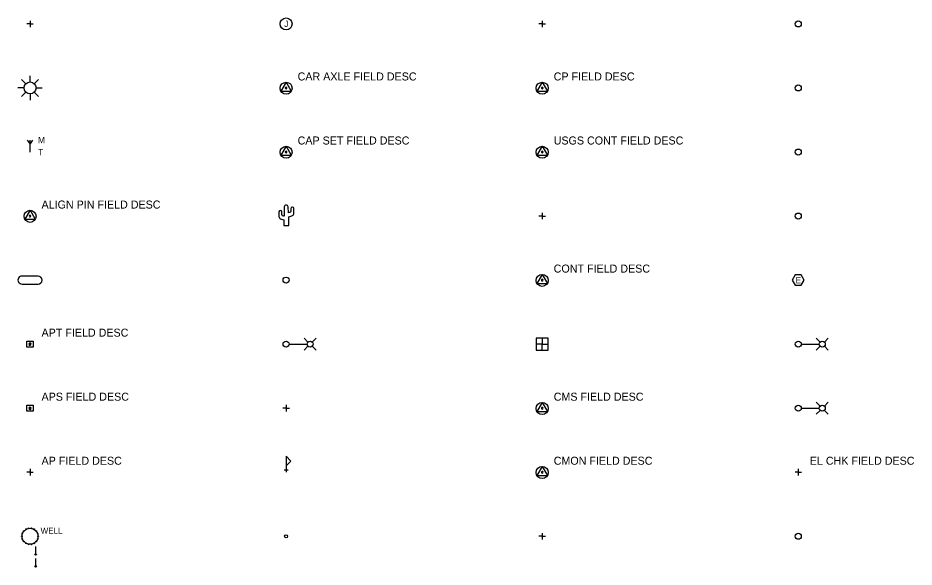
# Model space of a CAD drawing. Extents: x 91 to 2906, y -24 to 912.
# Drawn here: x 91 to 790, y -24 to 405 of the extents above; entities that cross this region are included whole.
import ezdxf

# ---------------------------------------------------------------- set-up
doc = ezdxf.new("R2010")
doc.units = 0
for name, color, linetype in [('B-BORE-CONE', 7, 'Continuous'), ('V-AERI-PNPT', 7, 'Continuous'), ('V-AFLD-DEVC', 7, 'Continuous'), ('V-CHAN-NAID', 7, 'Continuous'), ('V-COMM-ANTN', 7, 'Continuous'), ('V-COMM-JBOX', 7, 'Continuous'), ('V-CTRL-BMRK', 7, 'Continuous'), ('V-CTRL-HVPT', 7, 'Continuous'), ('V-CTRL-VERT', 7, 'Continuous'), ('V-FUEL-DEVC', 7, 'Continuous'), ('V-POWR-METR', 7, 'Continuous'), ('V-POWR-POLE', 7, 'Continuous'), ('V-RAIL-EQPM', 7, 'Continuous'), ('V-SITE-OTLN', 7, 'Continuous'), ('V-SITE-STRC', 7, 'Continuous'), ('V-SITE-VEGE', 7, 'Continuous'), ('V-SURV-DATA', 7, 'Continuous'), ('V-TOPO-SPOT', 7, 'Continuous')]:
    doc.layers.add(name, color=color, linetype=linetype)

msp = doc.modelspace()

# ---------------------------------------------------------------- linework, layer by layer
at = {"layer": 'B-BORE-CONE'}
for points in [[(495.31, 145.31), (504.69, 145.31), (504.69, 154.69), (495.31, 154.69)], [(500, 150), (504.69, 150), (504.69, 154.69), (500, 154.69)], [(495.31, 145.31), (500, 145.31), (500, 150), (495.31, 150)]]:
    msp.add_lwpolyline(points, close=True, dxfattribs=at)
at = {"layer": 'V-AERI-PNPT'}
for p, q in [((99.53, 150), (100.47, 150)), ((99.53, 100), (100.47, 100))]:
    msp.add_line(p, q, dxfattribs=at)
for points in [[(97.58, 152.42), (102.42, 152.42), (102.42, 147.58), (97.58, 147.58)], [(97.58, 102.42), (102.42, 102.42), (102.42, 97.58), (97.58, 97.58)]]:
    msp.add_lwpolyline(points, close=True, dxfattribs=at)
for centre, radius, start, end in [((100, 150), 0.909, 91.4818, 90.9603), ((100, 150), 0.455, 95.64757, 94.60838), ((100, 100), 0.909, 91.4818, 90.9603), ((100, 100), 0.455, 95.64757, 94.60838)]:
    msp.add_arc(centre, radius, start, end, dxfattribs=at)
at = {"layer": 'V-AFLD-DEVC'}
for p, q in [((100, 354.69), (100, 359.44)), ((95.31, 350), (90.56, 350)), ((96.69, 353.31), (93.31, 356.69)), ((103.31, 353.31), (106.69, 356.69)), ((104.69, 350), (109.44, 350)), ((96.69, 346.69), (93.31, 343.31)), ((100, 345.31), (100, 340.56)), ((103.31, 346.69), (106.69, 343.31))]:
    msp.add_line(p, q, dxfattribs=at)
msp.add_circle((100, 350), 4.69, dxfattribs=at)
at = {"layer": 'V-CHAN-NAID'}
for p, q in [((298.54, 51.91), (301.66, 51.91)), ((300, 54.98), (300, 50))]:
    msp.add_line(p, q, dxfattribs=at)
msp.add_lwpolyline([(300, 54.98), (303.76, 58.75), (300, 62.51)], close=True, dxfattribs=at)
at = {"layer": 'V-COMM-ANTN'}
msp.add_line((100, 300), (100, 309.37), dxfattribs=at)
msp.add_lwpolyline([(97.88, 309.37), (100, 306.19), (102.12, 309.37)], dxfattribs=at)
at = {"layer": 'V-COMM-JBOX'}
msp.add_circle((300, 400), 4.69, dxfattribs=at)
at = {"layer": 'V-FUEL-DEVC'}
for p, q in [((93.65, 0), (93.65, 0)), ((94.03, 2.18), (94.03, 2.18)), ((95.13, 4.09), (95.13, 4.09)), ((96.82, 5.5), (96.82, 5.5)), ((98.9, 6.25), (98.9, 6.25)), ((101.11, 6.25), (101.11, 6.25)), ((103.18, 5.5), (103.18, 5.5)), ((104.87, 4.09), (104.87, 4.09)), ((105.97, 2.18), (105.97, 2.18)), ((106.35, 0), (106.35, 0)), ((94.03, -2.18), (94.03, -2.18)), ((95.13, -4.09), (95.13, -4.09)), ((96.82, -5.5), (96.82, -5.5)), ((98.9, -6.25), (98.9, -6.25)), ((101.11, -6.25), (101.11, -6.25)), ((103.18, -5.5), (103.18, -5.5)), ((104.87, -4.09), (104.87, -4.09)), ((105.97, -2.18), (105.97, -2.18)), ((104.42, -7.94), (104.42, -13.59)), ((104.42, -17.24), (104.42, -22.89))]:
    msp.add_line(p, q, dxfattribs=at)
for centre, radius in [((93.65, 0), 0.282), ((94.03, 2.17), 0.282), ((100, 0), 6.24), ((95.14, 4.08), 0.282), ((96.83, 5.5), 0.282), ((98.9, 6.25), 0.282), ((101.1, 6.25), 0.282), ((103.18, 5.5), 0.282), ((104.86, 4.08), 0.282), ((105.97, 2.17), 0.282), ((106.35, 0), 0.282), ((94.03, -2.17), 0.282), ((95.14, -4.08), 0.282), ((96.83, -5.5), 0.282), ((98.9, -6.25), 0.282), ((101.1, -6.25), 0.282), ((103.18, -5.5), 0.282), ((104.86, -4.08), 0.282), ((105.97, -2.17), 0.282), ((104.42, -14.15), 0.564), ((104.42, -23.46), 0.564)]:
    msp.add_circle(centre, radius, dxfattribs=at)
at = {"layer": 'V-POWR-METR'}
msp.add_lwpolyline([(702.34, 195.94), (704.69, 200), (702.34, 204.06), (697.66, 204.06), (695.31, 200), (697.66, 195.94)], close=True, dxfattribs=at)
at = {"layer": 'V-POWR-POLE'}
for centre in [(700, 400), (700, 350), (700, 300), (700, 250), (300, 200), (700, 0)]:
    msp.add_circle(centre, 2.34, dxfattribs=at)
at = {"layer": 'V-RAIL-EQPM'}
msp.add_circle((300, 0), 1.17, dxfattribs=at)
at = {"layer": 'V-SITE-OTLN'}
for p, q in [((317.09, 151.66), (314.06, 154.69)), ((320.41, 151.66), (323.44, 154.69)), ((717.09, 151.66), (714.06, 154.69)), ((720.41, 151.66), (723.44, 154.69)), ((302.34, 150), (316.41, 150)), ((317.09, 148.34), (314.06, 145.31)), ((320.41, 148.34), (323.44, 145.31)), ((702.34, 150), (716.41, 150)), ((717.09, 148.34), (714.06, 145.31)), ((720.41, 148.34), (723.44, 145.31)), ((300, 100), (297.46, 100)), ((300, 102.55), (300, 97.46)), ((300, 100), (302.55, 100)), ((702.34, 100), (716.41, 100)), ((717.09, 101.66), (714.06, 104.69)), ((717.09, 98.34), (714.06, 95.31)), ((720.41, 101.66), (723.44, 104.69)), ((720.41, 98.34), (723.44, 95.31))]:
    msp.add_line(p, q, dxfattribs=at)
for centre in [(300, 150), (318.75, 150), (700, 150), (718.75, 150), (700, 100), (718.75, 100)]:
    msp.add_circle(centre, 2.34, dxfattribs=at)
at = {"layer": 'V-SITE-STRC'}
for p, q in [((106.25, 203.13), (93.75, 203.13)), ((93.75, 196.87), (106.25, 196.87))]:
    msp.add_line(p, q, dxfattribs=at)
for centre, start_param, end_param in [((93.75, 200), 0, 3.141593), ((106.25, 200), 3.141593, 6.283185)]:
    msp.add_ellipse(centre, major_axis=(0, 3.13), ratio=0.999658, start_param=start_param, end_param=end_param, dxfattribs=at)
at = {"layer": 'V-SITE-VEGE'}
for p, q in [((294.44, 253.39), (294.45, 249.71)), ((296.66, 250.94), (296.65, 253.32)), ((303.8, 255.81), (303.72, 253.54)), ((306.02, 251.72), (306.03, 255.51))]:
    msp.add_line(p, q, dxfattribs=at)
for points in [[(298.62, 257.19), (298.42, 250.01), (297.64, 250.08)], [(303.49, 253.09), (301.77, 252.48), (301.62, 257.18)], [(295.48, 247.92), (298.21, 247.02), (298.21, 242.64)], [(298.21, 242.64), (302.05, 242.64), (302.05, 249.51), (304.59, 250.31)]]:
    msp.add_lwpolyline(points, dxfattribs=at)
for centre, radius, start, end in [((295.54, 253.22), 1.11, 4.76961, 171.44108), ((300.12, 257.13), 1.5, 1.87586, 177.61223), ((303.07, 253.6), 0.659, 310.24132, 354.97177), ((304.94, 255.83), 1.14, 343.59093, 180.84359), ((296.35, 249.61), 1.9, 176.81617, 242.70551), ((297.74, 251.18), 1.1, 192.63471, 264.81207), ((304.49, 251.84), 1.53, 273.60935, 355.59578)]:
    msp.add_arc(centre, radius, start, end, dxfattribs=at)
at = {"layer": 'V-SURV-DATA'}
for p, q in [((300, 354.48), (295.95, 347.46)), ((300, 354.48), (304.05, 347.46)), ((500, 354.48), (495.95, 347.46)), ((500, 354.48), (504.05, 347.46)), ((295.95, 347.46), (304.05, 347.46)), ((495.95, 347.46), (504.05, 347.46)), ((300, 304.48), (295.95, 297.46)), ((300, 304.48), (304.05, 297.46)), ((500, 304.48), (495.95, 297.46)), ((500, 304.48), (504.05, 297.46)), ((295.95, 297.46), (304.05, 297.46)), ((495.95, 297.46), (504.05, 297.46)), ((100, 254.48), (95.95, 247.46)), ((100, 254.48), (104.05, 247.46)), ((95.95, 247.46), (104.05, 247.46)), ((500, 204.48), (495.95, 197.46)), ((500, 204.48), (504.05, 197.46)), ((495.95, 197.46), (504.05, 197.46)), ((500, 104.48), (495.95, 97.46)), ((500, 104.48), (504.05, 97.46)), ((495.95, 97.46), (504.05, 97.46)), ((100, 50), (97.46, 50)), ((100, 52.55), (100, 47.46)), ((100, 50), (102.55, 50)), ((500, 54.48), (495.95, 47.46)), ((500, 54.48), (504.05, 47.46)), ((700, 50), (697.46, 50)), ((700, 52.55), (700, 47.46)), ((700, 50), (702.55, 50)), ((495.95, 47.46), (504.05, 47.46)), ((500, 2.55), (500, -2.54)), ((500, 0), (497.46, 0)), ((500, 0), (502.55, 0))]:
    msp.add_line(p, q, dxfattribs=at)
for centre in [(300, 349.8), (500, 349.8), (300, 299.8), (500, 299.8), (100, 249.8), (500, 199.8), (500, 99.8), (500, 49.8)]:
    msp.add_circle(centre, 4.69, dxfattribs=at)
for centre in [(300, 350), (500, 350), (300, 300), (500, 300), (100, 250), (500, 200), (500, 100), (500, 50)]:
    msp.add_arc(centre, 0.65, 92.28772, 90.56743, dxfattribs=at)
at = {"layer": 'V-TOPO-SPOT'}
for p, q in [((100, 400), (97.46, 400)), ((100, 402.55), (100, 397.46)), ((100, 400), (102.55, 400)), ((500, 400), (497.46, 400)), ((500, 402.55), (500, 397.46)), ((500, 400), (502.55, 400)), ((500, 252.55), (500, 247.46)), ((500, 250), (497.46, 250)), ((500, 250), (502.55, 250))]:
    msp.add_line(p, q, dxfattribs=at)

# ---------------------------------------------------------------- texts
at = {"layer": 'V-AERI-PNPT'}
for s, p in [('APT FIELD DESC', (109, 155.87)), ('APS FIELD DESC', (109, 105.87)), ('AP FIELD DESC', (109, 55.87))]:
    msp.add_text(s, height=6.252, dxfattribs=at).set_placement(p)
at = {"layer": 'V-COMM-ANTN'}
for s, p in [('M', (106.25, 306.91)), ('T', (106.25, 297.54))]:
    msp.add_text(s, height=4.92, dxfattribs=at).set_placement(p)
at = {"layer": 'V-COMM-JBOX'}
msp.add_text('J', height=4.92, dxfattribs=at).set_placement((298.55, 397.54))
at = {"layer": 'V-CTRL-BMRK'}
for s, p in [('USGS CONT FIELD DESC', (509, 305.87)), ('CONT FIELD DESC', (509, 205.87))]:
    msp.add_text(s, height=6.252, dxfattribs=at).set_placement(p)
at = {"layer": 'V-CTRL-HVPT'}
msp.add_text('CP FIELD DESC', height=6.252, dxfattribs=at).set_placement((509, 355.87))
at = {"layer": 'V-CTRL-VERT'}
msp.add_text('EL CHK FIELD DESC', height=6.252, dxfattribs=at).set_placement((709, 55.87))
at = {"layer": 'V-FUEL-DEVC'}
msp.add_text('WELL', height=4.68, dxfattribs=at).set_placement((108.31, 1.93))
at = {"layer": 'V-POWR-METR'}
msp.add_text('E', height=4.92, dxfattribs=at).set_placement((697.89, 197.54))
at = {"layer": 'V-SURV-DATA'}
for s, p in [('CAR AXLE FIELD DESC', (309, 355.87)), ('CAP SET FIELD DESC', (309, 305.87)), ('ALIGN PIN FIELD DESC', (109, 255.87)), ('CMS FIELD DESC', (509, 105.87)), ('CMON FIELD DESC', (509, 55.87))]:
    msp.add_text(s, height=6.252, dxfattribs=at).set_placement(p)

doc.saveas('drawing.dxf')
